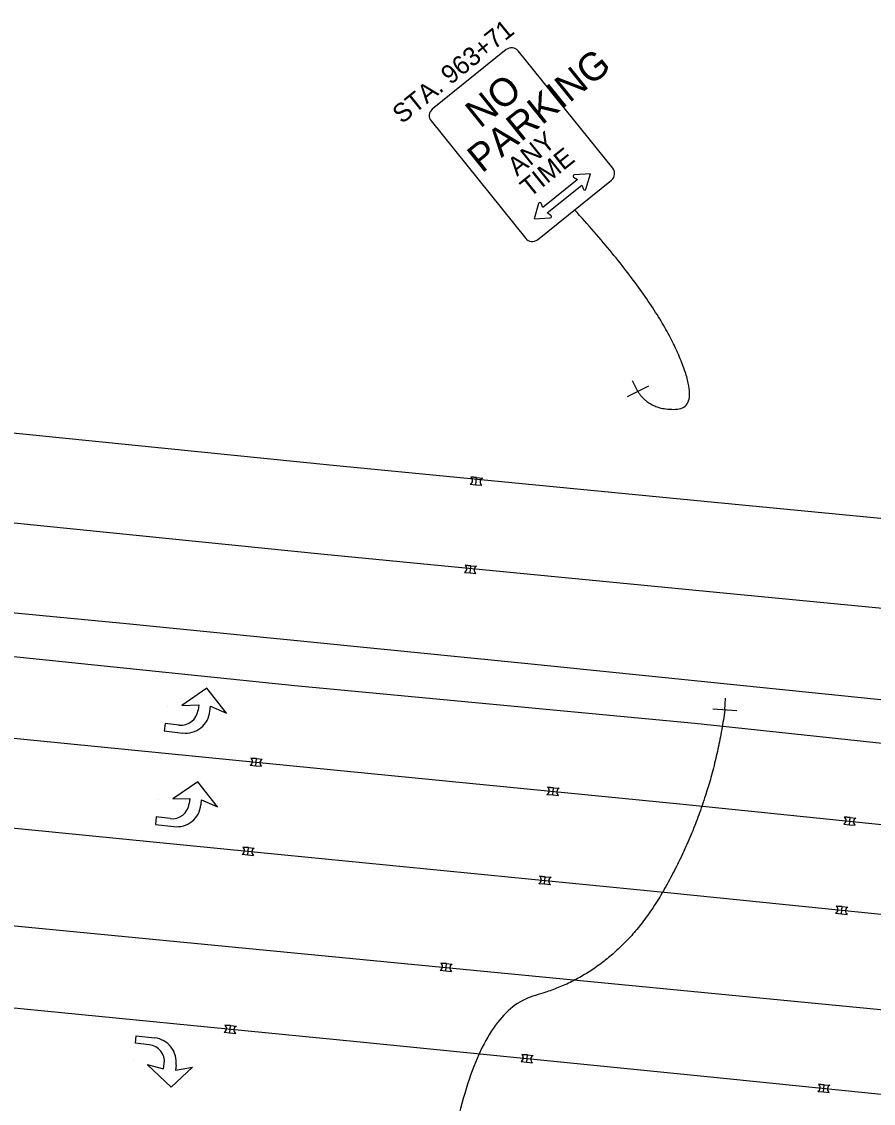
# Model space of a CAD drawing. Extents: x 1847379 to 1850904, y 217032 to 220169.
# Drawn here: x 1850426.1 to 1850540.3, y 218683.8 to 218829 of the extents above; entities that cross this region are included whole.
import ezdxf

# ---------------------------------------------------------------- set-up
doc = ezdxf.new("R2010")
doc.units = 0
for name, color, linetype in [('PM_P_Cells', 7, 'Continuous'), ('PM_P_Channelizing_Line', 7, 'Continuous'), ('PM_P_Edge_Line', 7, 'Continuous'), ('PM_P_Lane_Line', 7, 'Continuous'), ('SN_X_Public', 7, 'Continuous')]:
    doc.layers.add(name, color=color, linetype=linetype)

msp = doc.modelspace()

# ---------------------------------------------------------------- linework, layer by layer
at = {"layer": 'PM_P_Cells'}
for p, q in [((1850486.23, 218766.92), (1850487, 218766.85)), ((1850486.23, 218766.92), (1850487, 218766.85)), ((1850487.09, 218767.82), (1850486.32, 218767.89)), ((1850486.32, 218767.89), (1850487.09, 218767.82)), ((1850487, 218766.85), (1850487.09, 218767.82)), ((1850487.09, 218767.82), (1850487.86, 218767.75)), ((1850487, 218766.85), (1850487.77, 218766.78)), ((1850486.3, 218755.98), (1850485.53, 218756.05)), ((1850485.53, 218756.05), (1850486.3, 218755.98)), ((1850486.21, 218755.01), (1850486.3, 218755.98)), ((1850486.3, 218755.98), (1850487.07, 218755.91)), ((1850485.44, 218755.08), (1850486.21, 218755.01)), ((1850485.44, 218755.08), (1850486.21, 218755.01)), ((1850486.21, 218755.01), (1850486.98, 218754.94)), ((1850450.88, 218739.53), (1850447.54, 218737.24)), ((1850453.54, 218736.19), (1850450.88, 218739.53)), ((1850445.6, 218737.14), (1850445.6, 218737.14)), ((1850447.54, 218737.24), (1850449.81, 218737.31)), ((1850449.81, 218737.31), (1850449.72, 218736.61)), ((1850451.32, 218736.46), (1850451.4, 218737.12)), ((1850451.4, 218737.12), (1850453.54, 218736.19)), ((1850453.54, 218736.19), (1850453.54, 218736.19)), ((1850445.32, 218734.82), (1850445.2, 218733.83)), ((1850445.2, 218733.83), (1850447.66, 218733.53)), ((1850447.17, 218734.6), (1850445.32, 218734.82)), ((1850456.72, 218729.2), (1850457.48, 218729.13)), ((1850456.72, 218729.2), (1850457.48, 218729.13)), ((1850457.57, 218730.1), (1850456.8, 218730.17)), ((1850456.8, 218730.17), (1850457.57, 218730.1)), ((1850457.48, 218729.13), (1850457.57, 218730.1)), ((1850457.48, 218729.13), (1850458.25, 218729.06)), ((1850457.57, 218730.1), (1850458.34, 218730.03)), ((1850449.68, 218726.97), (1850446.34, 218724.68)), ((1850452.34, 218723.63), (1850449.68, 218726.97)), ((1850497.38, 218726.19), (1850496.61, 218726.26)), ((1850496.61, 218726.26), (1850497.38, 218726.19)), ((1850496.52, 218725.29), (1850497.29, 218725.22)), ((1850496.52, 218725.29), (1850497.29, 218725.22)), ((1850497.29, 218725.22), (1850497.38, 218726.19)), ((1850497.29, 218725.22), (1850498.06, 218725.15)), ((1850497.38, 218726.19), (1850498.15, 218726.12)), ((1850444.4, 218724.58), (1850444.4, 218724.58)), ((1850446.34, 218724.68), (1850448.61, 218724.74)), ((1850448.61, 218724.74), (1850448.52, 218724.05)), ((1850450.12, 218723.89), (1850450.2, 218724.55)), ((1850450.2, 218724.55), (1850452.34, 218723.63)), ((1850452.34, 218723.63), (1850452.34, 218723.63)), ((1850444.12, 218722.26), (1850444, 218721.27)), ((1850445.97, 218722.04), (1850444.12, 218722.26)), ((1850537.18, 218722.19), (1850536.41, 218722.26)), ((1850536.41, 218722.26), (1850537.18, 218722.19)), ((1850537.09, 218721.22), (1850537.18, 218722.19)), ((1850537.18, 218722.19), (1850537.95, 218722.12)), ((1850444, 218721.27), (1850446.46, 218720.97)), ((1850536.32, 218721.28), (1850537.09, 218721.22)), ((1850536.32, 218721.28), (1850537.09, 218721.22)), ((1850537.09, 218721.22), (1850537.86, 218721.15)), ((1850456.49, 218718.15), (1850455.72, 218718.22)), ((1850455.72, 218718.22), (1850456.49, 218718.15)), ((1850456.4, 218717.18), (1850456.49, 218718.15)), ((1850456.49, 218718.15), (1850457.26, 218718.08)), ((1850455.63, 218717.25), (1850456.4, 218717.18)), ((1850455.63, 218717.25), (1850456.4, 218717.18)), ((1850456.4, 218717.18), (1850457.17, 218717.11)), ((1850495.44, 218713.34), (1850496.21, 218713.27)), ((1850495.44, 218713.34), (1850496.21, 218713.27)), ((1850496.3, 218714.24), (1850495.53, 218714.31)), ((1850495.53, 218714.31), (1850496.3, 218714.24)), ((1850496.21, 218713.27), (1850496.3, 218714.24)), ((1850496.21, 218713.27), (1850496.98, 218713.2)), ((1850496.3, 218714.24), (1850497.07, 218714.17)), ((1850536.1, 218710.24), (1850535.33, 218710.31)), ((1850535.33, 218710.31), (1850536.1, 218710.24)), ((1850535.24, 218709.33), (1850536.01, 218709.26)), ((1850535.24, 218709.33), (1850536.01, 218709.26)), ((1850536.01, 218709.26), (1850536.1, 218710.24)), ((1850536.01, 218709.26), (1850536.78, 218709.19)), ((1850536.1, 218710.24), (1850536.87, 218710.17)), ((1850482.19, 218701.68), (1850482.96, 218701.61)), ((1850482.19, 218701.68), (1850482.96, 218701.61)), ((1850483.05, 218702.58), (1850482.28, 218702.65)), ((1850482.28, 218702.65), (1850483.05, 218702.58)), ((1850482.96, 218701.61), (1850483.05, 218702.58)), ((1850482.96, 218701.61), (1850483.73, 218701.54)), ((1850483.05, 218702.58), (1850483.82, 218702.51)), ((1850454.09, 218694.26), (1850453.32, 218694.33)), ((1850453.32, 218694.33), (1850454.09, 218694.26)), ((1850441.32, 218691.91), (1850441.43, 218692.9)), ((1850441.43, 218692.9), (1850443.89, 218692.62)), ((1850453.23, 218693.36), (1850454, 218693.29)), ((1850453.23, 218693.36), (1850454, 218693.29)), ((1850454, 218693.29), (1850454.09, 218694.26)), ((1850454, 218693.29), (1850454.77, 218693.22)), ((1850454.09, 218694.26), (1850454.86, 218694.19)), ((1850443.17, 218691.69), (1850441.32, 218691.91)), ((1850493.89, 218690.32), (1850493.13, 218690.39)), ((1850493.13, 218690.39), (1850493.89, 218690.32)), ((1850493.81, 218689.35), (1850493.89, 218690.32)), ((1850493.89, 218690.32), (1850494.66, 218690.25)), ((1850441.05, 218689.59), (1850441.05, 218689.59)), ((1850446.11, 218685.99), (1850442.92, 218689.04)), ((1850442.92, 218689.04), (1850445.11, 218688.45)), ((1850445.11, 218688.45), (1850445.19, 218689.15)), ((1850449, 218688.68), (1850446.11, 218685.99)), ((1850446.77, 218688.93), (1850446.7, 218688.27)), ((1850446.7, 218688.27), (1850449, 218688.68)), ((1850449, 218688.68), (1850449, 218688.68)), ((1850493.04, 218689.42), (1850493.81, 218689.35)), ((1850493.04, 218689.42), (1850493.81, 218689.35)), ((1850493.81, 218689.35), (1850494.57, 218689.28)), ((1850533.69, 218686.33), (1850532.93, 218686.4)), ((1850532.93, 218686.4), (1850533.69, 218686.33)), ((1850533.61, 218685.36), (1850533.69, 218686.33)), ((1850533.69, 218686.33), (1850534.46, 218686.26)), ((1850532.84, 218685.43), (1850533.61, 218685.36)), ((1850532.84, 218685.43), (1850533.61, 218685.36)), ((1850533.61, 218685.36), (1850534.37, 218685.29))]:
    msp.add_line(p, q, dxfattribs=at)
for centre, radius, start, end in [((1850485.97, 218767.43), 0.576, 296.8063, 52.8586), ((1850485.97, 218767.43), 0.576, 296.8063, 52.8586), ((1850488.12, 218767.24), 0.576, 116.8063, 232.8586), ((1850485.18, 218755.59), 0.576, 296.8063, 52.8586), ((1850485.18, 218755.59), 0.576, 296.8063, 52.8586), ((1850487.33, 218755.4), 0.576, 116.8063, 232.8586), ((1850447.44, 218736.88), 2.3, 263.1824, 353.1824), ((1850448.05, 218736.79), 3.28, 263.1824, 354.0909), ((1850456.46, 218729.71), 0.576, 296.8063, 52.8586), ((1850456.46, 218729.71), 0.576, 296.8063, 52.8586), ((1850458.6, 218729.52), 0.576, 116.8063, 232.8586), ((1850496.26, 218725.8), 0.576, 296.8063, 52.8586), ((1850496.26, 218725.8), 0.576, 296.8063, 52.8586), ((1850498.41, 218725.61), 0.576, 116.8063, 232.8586), ((1850446.24, 218724.32), 2.3, 263.1824, 353.1824), ((1850446.85, 218724.23), 3.28, 263.1824, 354.0909), ((1850536.06, 218721.8), 0.576, 296.8063, 52.8586), ((1850536.06, 218721.8), 0.576, 296.8063, 52.8586), ((1850538.21, 218721.6), 0.576, 116.8063, 232.8586), ((1850455.38, 218717.76), 0.576, 296.8063, 52.8586), ((1850455.38, 218717.76), 0.576, 296.8063, 52.8586), ((1850457.52, 218717.57), 0.576, 116.8063, 232.8586), ((1850495.18, 218713.85), 0.576, 296.8063, 52.8586), ((1850495.18, 218713.85), 0.576, 296.8063, 52.8586), ((1850497.33, 218713.66), 0.576, 116.8063, 232.8586), ((1850534.98, 218709.85), 0.576, 296.8063, 52.8586), ((1850534.98, 218709.85), 0.576, 296.8063, 52.8586), ((1850537.13, 218709.65), 0.576, 116.8063, 232.8586), ((1850481.94, 218702.19), 0.576, 296.8063, 52.8586), ((1850481.94, 218702.19), 0.576, 296.8063, 52.8586), ((1850484.08, 218702), 0.576, 116.8063, 232.8586), ((1850452.97, 218693.87), 0.576, 296.8063, 52.8586), ((1850452.97, 218693.87), 0.576, 296.8063, 52.8586), ((1850455.11, 218693.68), 0.576, 116.8063, 232.8586), ((1850442.91, 218689.41), 2.3, 353.453, 83.453), ((1850443.52, 218689.36), 3.28, 352.5446, 83.453), ((1850492.78, 218689.93), 0.576, 296.8063, 52.8586), ((1850492.78, 218689.93), 0.576, 296.8063, 52.8586), ((1850494.92, 218689.74), 0.576, 116.8063, 232.8586), ((1850532.58, 218685.94), 0.576, 296.8063, 52.8586), ((1850532.58, 218685.94), 0.576, 296.8063, 52.8586), ((1850534.72, 218685.75), 0.576, 116.8063, 232.8586)]:
    msp.add_arc(centre, radius, start, end, dxfattribs=at)
at = {"layer": 'PM_P_Channelizing_Line'}
for points in [[(1850652.98, 218698.12), (1850615.27, 218701.75), (1850564.66, 218706.78), (1850513.12, 218712.05), (1850461.3, 218717.14), (1850408.88, 218722.34), (1850360.86, 218727.03), (1850313.39, 218731.82), (1850265.8, 218736.37), (1849979.48, 218762.27)], [(1850654.14, 218710.06), (1850616.44, 218713.69), (1850565.86, 218718.72), (1850514.32, 218723.99), (1850462.47, 218729.08), (1850410.06, 218734.29), (1850362.04, 218738.97), (1850314.56, 218743.77), (1850266.91, 218748.32), (1850234.59, 218751.24)], [(1850650.65, 218674.09), (1850566.02, 218682.53), (1850518.02, 218687.39), (1850471.03, 218692.07), (1850419.06, 218697.16), (1850371.65, 218702.19), (1850311.6, 218707.75), (1850264.65, 218712.06), (1850215.84, 218717), (1850171.13, 218721.51), (1850121.19, 218725.85), (1850066.37, 218730.8), (1850014.99, 218735.41), (1849965.69, 218739.72), (1849914.21, 218744.36), (1849896.49, 218746.14)]]:
    msp.add_lwpolyline(points, dxfattribs=at)
at = {"layer": 'PM_P_Edge_Line'}
for p, q in [((1850388.94, 218753.21), (1850440.13, 218748.21)), ((1850440.13, 218748.21), (1850494.86, 218742.76)), ((1850462.7, 218739.86), (1850410.97, 218745.19)), ((1850494.86, 218742.76), (1850542.59, 218737.91)), ((1850516.36, 218734.8), (1850462.7, 218739.86)), ((1850565.85, 218729.5), (1850516.36, 218734.8))]:
    msp.add_line(p, q, dxfattribs=at)
msp.add_lwpolyline([(1849889.22, 218821.46), (1849908.57, 218819.63), (1849959.34, 218815.75), (1850016.54, 218811.11), (1850069.2, 218806.62), (1850120.11, 218802.11), (1850169.53, 218797.86), (1850218.84, 218793.6), (1850268.16, 218788.98), (1850318.46, 218784.1), (1850367.53, 218779.29), (1850417.75, 218774.53), (1850467.84, 218769.49), (1850519.01, 218764.5), (1850567.74, 218759.83), (1850617.52, 218754.84), (1850666.94, 218749.6)], dxfattribs=at)
at = {"layer": 'PM_P_Lane_Line'}
msp.add_line((1849881.96, 218760.04), (1850650.78, 218685.87), dxfattribs=at)
msp.add_lwpolyline([(1849608.99, 218828.81), (1849660.31, 218825.18), (1849710.18, 218821.58), (1849761.09, 218817.87), (1849808.06, 218814.41), (1849858.45, 218811.1), (1849907.69, 218807.67), (1849958.4, 218803.79), (1850015.55, 218799.15), (1850068.16, 218794.66), (1850119.07, 218790.16), (1850168.5, 218785.91), (1850217.76, 218781.65), (1850267.02, 218777.03), (1850317.3, 218772.15), (1850366.38, 218767.35), (1850416.59, 218762.59), (1850466.65, 218757.55), (1850517.86, 218752.55), (1850566.57, 218747.88), (1850616.29, 218742.91), (1850664.9, 218737.75)], dxfattribs=at)
at = {"layer": 'SN_X_Public'}
for p, q in [((1850500.59, 218807.79), (1850495.96, 218804.06)), ((1850500.1, 218808.13), (1850500.6, 218807.8)), ((1850502.35, 218808.6), (1850500.19, 218808.46)), ((1850500.6, 218807.8), (1850500.59, 218807.79)), ((1850501.75, 218806.52), (1850502.35, 218808.6)), ((1850501.19, 218807.07), (1850501.4, 218806.51)), ((1850495.96, 218804.06), (1850495.75, 218804.62)), ((1850498.77, 218805.49), (1850498.77, 218805.49)), ((1850495.4, 218804.6), (1850494.8, 218802.52)), ((1850495.96, 218804.06), (1850495.97, 218804.07)), ((1850497.05, 218803), (1850496.55, 218803.33)), ((1850494.8, 218802.52), (1850496.96, 218802.67)), ((1850510.13, 218780.07), (1850507.26, 218778.67)), ((1850508.7, 218779.37), (1850507.99, 218780.81)), ((1850520.37, 218736.61), (1850520.48, 218738.2)), ((1850521.97, 218736.5), (1850518.78, 218736.71))]:
    msp.add_line(p, q, dxfattribs=at)
for points in [[(1850491.06, 218825.26), (1850481.14, 218817.26)], [(1850505.35, 218809.32), (1850492.64, 218825.09)], [(1850480.97, 218815.67), (1850493.67, 218799.91)], [(1850495.25, 218799.74), (1850505.18, 218807.74)], [(1850496.55, 218803.33), (1850501.18, 218807.06)]]:
    msp.add_lwpolyline(points, dxfattribs=at)
for centre, radius, start, end in [((1850491.77, 218824.38), 1.12, 38.8676, 128.8676), ((1850481.84, 218816.38), 1.12, 128.8676, 218.8676), ((1850504.48, 218808.62), 1.12, 308.8676, 38.8676), ((1850500.2, 218808.28), 0.182, 93.7884, 236.5054), ((1850501.57, 218806.57), 0.182, 201.2298, 343.9469), ((1850495.58, 218804.55), 0.182, 21.2298, 163.9469), ((1850496.95, 218802.85), 0.182, 273.7884, 56.5054), ((1850494.55, 218800.61), 1.12, 218.8676, 308.8676)]:
    msp.add_arc(centre, radius, start, end, dxfattribs=at)
for points in [[(1850508.7, 218779.37), (1850510.34, 218776.81), (1850517.41, 218777.17), (1850510.42, 218792.57), (1850500.22, 218803.74)], [(1850520.37, 218736.61), (1850518.63, 218723.82), (1850505.88, 218701.29), (1850484.26, 218695.43), (1850482.13, 218662.98)]]:
    msp.add_open_spline(points, degree=2, dxfattribs=at)

# ---------------------------------------------------------------- texts
for s, height, p in [('STA. 963+71', 2.5, (1850477.07, 218815.21)), ('PARKING', 3.75, (1850487.8, 218808.58)), ('NO', 3.75, (1850487.55, 218814.6)), ('ANY', 2.5, (1850492.51, 218808.17)), ('TIME', 2.5, (1850494.22, 218805.33))]:
    msp.add_text(s, height=height, rotation=38.8676, dxfattribs=at).set_placement(p)

doc.saveas('drawing.dxf')
